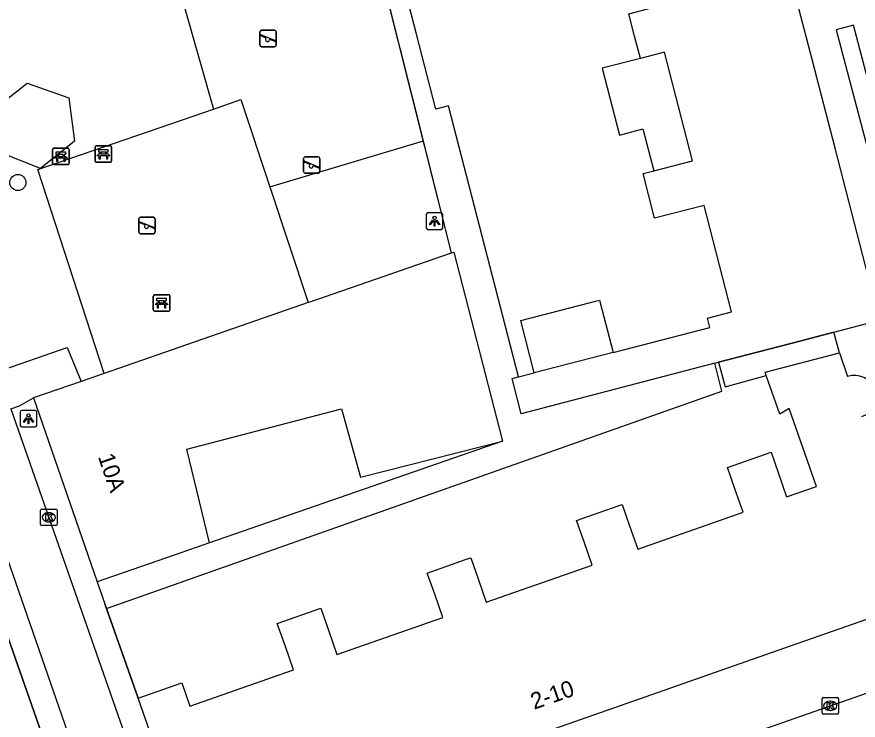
# Model space of a CAD drawing. Extents: x 159377 to 159983, y 382996 to 383595.
# Drawn here: x 159638.5 to 159689.6, y 383315.4 to 383358.1 of the extents above; entities that cross this region are included whole.
import ezdxf

# ---------------------------------------------------------------- set-up
doc = ezdxf.new("R2010")
doc.units = 0
for name, color, linetype in [('IMGEO_Bank', 7, 'Continuous'), ('IMGEO_Boom', 7, 'Continuous'), ('IMGEO_Groenvoorziening', 7, 'Continuous'), ('IMGEO_Hek', 7, 'Continuous'), ('IMGEO_Kolk', 7, 'Continuous'), ('IMGEO_Lichtpunt', 7, 'Continuous'), ('IMGEO_Muur', 7, 'Continuous'), ('IMGEO_Pand', 7, 'Continuous'), ('IMGEO_Pand_nummerreeks', 7, 'Continuous'), ('IMGEO_Pand_overbouw', 7, 'Continuous'), ('IMGEO_Rijbaan_lokaal_open', 7, 'Continuous'), ('IMGEO_Speelvoorziening', 7, 'Continuous'), ('IMGEO_Terreindeel_gesloten', 7, 'Continuous'), ('IMGEO_Voetpad_open', 7, 'Continuous')]:
    doc.layers.add(name, color=color, linetype=linetype)

msp = doc.modelspace()

# ---------------------------------------------------------------- linework, layer by layer
at = {"layer": 'IMGEO_Bank'}
for p, q in [((159643.349, 383350.24), (159644.19, 383350.24)), ((159644.19, 383350.24), (159643.349, 383350.24)), ((159640.697, 383349.171), (159640.697, 383350.012)), ((159640.697, 383350.012), (159640.697, 383349.171)), ((159640.772, 383350.096), (159641.613, 383350.096)), ((159641.613, 383350.096), (159640.772, 383350.096)), ((159641.338, 383349.714), (159641.056, 383349.714)), ((159641.697, 383350.021), (159641.697, 383349.18)), ((159641.697, 383349.18), (159641.697, 383350.021)), ((159643.274, 383349.315), (159643.274, 383350.156)), ((159643.274, 383350.156), (159643.274, 383349.315)), ((159643.583, 383349.746), (159643.583, 383349.852)), ((159643.627, 383349.852), (159643.627, 383349.746)), ((159643.915, 383349.858), (159643.633, 383349.858)), ((159643.633, 383349.74), (159643.915, 383349.74)), ((159643.921, 383349.746), (159643.921, 383349.852)), ((159643.965, 383349.852), (159643.965, 383349.746)), ((159644.274, 383350.165), (159644.274, 383349.324)), ((159644.274, 383349.324), (159644.274, 383350.165)), ((159641.394, 383349.494), (159641.001, 383349.494)), ((159641.006, 383349.602), (159641.006, 383349.708)), ((159641.05, 383349.708), (159641.05, 383349.602)), ((159641.056, 383349.596), (159641.338, 383349.596)), ((159641.344, 383349.602), (159641.344, 383349.708)), ((159641.388, 383349.708), (159641.388, 383349.602)), ((159644.199, 383349.24), (159643.358, 383349.24)), ((159643.358, 383349.24), (159644.199, 383349.24)), ((159643.971, 383349.638), (159643.578, 383349.638)), ((159641.622, 383349.096), (159640.781, 383349.096)), ((159640.781, 383349.096), (159641.622, 383349.096)), ((159646.805, 383340.282), (159646.805, 383341.123)), ((159646.805, 383341.123), (159646.805, 383340.282)), ((159646.88, 383341.207), (159647.721, 383341.207)), ((159647.721, 383341.207), (159646.88, 383341.207)), ((159647.805, 383341.132), (159647.805, 383340.291)), ((159647.805, 383340.291), (159647.805, 383341.132)), ((159647.502, 383340.605), (159647.109, 383340.605)), ((159647.114, 383340.713), (159647.114, 383340.819)), ((159647.158, 383340.819), (159647.158, 383340.713)), ((159647.446, 383340.825), (159647.164, 383340.825)), ((159647.164, 383340.707), (159647.446, 383340.707)), ((159647.452, 383340.713), (159647.452, 383340.819)), ((159647.496, 383340.819), (159647.496, 383340.713)), ((159647.73, 383340.207), (159646.889, 383340.207)), ((159646.889, 383340.207), (159647.73, 383340.207))]:
    msp.add_line(p, q, dxfattribs=at)
for points in [[(159641, 383349.714), (159640.914, 383349.714), (159640.914, 383349.875), (159641.477, 383349.875), (159641.477, 383349.714), (159641.394, 383349.714)], [(159643.521, 383349.638), (159643.379, 383349.638), (159643.491, 383349.74), (159643.577, 383349.74)], [(159643.577, 383349.858), (159643.491, 383349.858), (159643.491, 383350.019), (159644.054, 383350.019), (159644.054, 383349.858), (159643.971, 383349.858)], [(159643.971, 383349.74), (159644.054, 383349.74), (159644.166, 383349.638), (159644.027, 383349.638)], [(159640.944, 383349.494), (159640.802, 383349.494), (159640.914, 383349.596), (159641, 383349.596)], [(159640.994, 383349.487), (159640.994, 383349.28), (159640.951, 383349.28), (159640.951, 383349.487)], [(159641.394, 383349.596), (159641.477, 383349.596), (159641.589, 383349.494), (159641.45, 383349.494)], [(159641.444, 383349.487), (159641.444, 383349.28), (159641.4, 383349.28), (159641.4, 383349.487)], [(159643.571, 383349.631), (159643.571, 383349.424), (159643.528, 383349.424), (159643.528, 383349.631)], [(159644.021, 383349.631), (159644.021, 383349.424), (159643.977, 383349.424), (159643.977, 383349.631)], [(159647.052, 383340.605), (159646.91, 383340.605), (159647.022, 383340.707), (159647.108, 383340.707)], [(159647.108, 383340.825), (159647.022, 383340.825), (159647.022, 383340.986), (159647.585, 383340.986), (159647.585, 383340.825), (159647.502, 383340.825)], [(159647.102, 383340.598), (159647.102, 383340.391), (159647.059, 383340.391), (159647.059, 383340.598)], [(159647.502, 383340.707), (159647.585, 383340.707), (159647.697, 383340.605), (159647.558, 383340.605)], [(159647.552, 383340.598), (159647.552, 383340.391), (159647.508, 383340.391), (159647.508, 383340.598)]]:
    msp.add_lwpolyline(points, dxfattribs=at)
for centre, radius, start, end in [((159643.352, 383350.162), 0.0779, 92.4484, 184.2845), ((159643.352, 383350.162), 0.0779, 92.4484, 184.2845), ((159644.196, 383350.162), 0.0779, 2.4484, 94.2845), ((159644.196, 383350.162), 0.0779, 2.4484, 94.2845), ((159640.775, 383350.018), 0.0779, 92.4484, 184.2845), ((159640.775, 383350.018), 0.0779, 92.4484, 184.2845), ((159640.999, 383349.707), 0.00671, 2.8957, 87.1043), ((159641.056, 383349.707), 0.00671, 92.8957, 177.1043), ((159641.338, 383349.707), 0.00671, 2.8957, 87.1043), ((159641.395, 383349.707), 0.00671, 92.8957, 177.1043), ((159641.619, 383350.018), 0.0779, 2.4484, 94.2845), ((159641.619, 383350.018), 0.0779, 2.4484, 94.2845), ((159643.576, 383349.851), 0.00671, 2.8957, 87.1043), ((159643.576, 383349.747), 0.00671, 272.8957, 357.1043), ((159643.633, 383349.851), 0.00671, 92.8957, 177.1043), ((159643.633, 383349.747), 0.00671, 182.8957, 267.1043), ((159643.915, 383349.851), 0.00671, 2.8957, 87.1043), ((159643.915, 383349.747), 0.00671, 272.8957, 357.1043), ((159643.972, 383349.851), 0.00671, 92.8957, 177.1043), ((159643.972, 383349.747), 0.00671, 182.8957, 267.1043), ((159640.944, 383349.487), 0.00671, 2.8957, 87.1043), ((159641.001, 383349.487), 0.00671, 92.8957, 177.1043), ((159640.999, 383349.603), 0.00671, 272.8957, 357.1043), ((159641.056, 383349.603), 0.00671, 182.8957, 267.1043), ((159641.338, 383349.603), 0.00671, 272.8957, 357.1043), ((159641.395, 383349.603), 0.00671, 182.8957, 267.1043), ((159641.393, 383349.487), 0.00671, 2.8957, 87.1043), ((159641.45, 383349.487), 0.00671, 92.8957, 177.1043), ((159643.352, 383349.318), 0.0779, 182.4484, 274.2845), ((159643.352, 383349.318), 0.0779, 182.4484, 274.2845), ((159643.521, 383349.631), 0.00671, 2.8957, 87.1043), ((159643.578, 383349.631), 0.00671, 92.8957, 177.1043), ((159643.97, 383349.631), 0.00671, 2.8957, 87.1043), ((159644.027, 383349.631), 0.00671, 92.8957, 177.1043), ((159644.196, 383349.318), 0.0779, 272.4484, 4.2845), ((159644.196, 383349.318), 0.0779, 272.4484, 4.2845), ((159640.775, 383349.174), 0.0779, 182.4484, 274.2845), ((159640.775, 383349.174), 0.0779, 182.4484, 274.2845), ((159641.619, 383349.174), 0.0779, 272.4484, 4.2845), ((159641.619, 383349.174), 0.0779, 272.4484, 4.2845), ((159646.883, 383341.129), 0.0779, 92.4484, 184.2845), ((159646.883, 383341.129), 0.0779, 92.4484, 184.2845), ((159647.727, 383341.129), 0.0779, 2.4484, 94.2845), ((159647.727, 383341.129), 0.0779, 2.4484, 94.2845), ((159647.052, 383340.598), 0.00671, 2.8957, 87.1043), ((159647.109, 383340.598), 0.00671, 92.8957, 177.1043), ((159647.107, 383340.818), 0.00671, 2.8957, 87.1043), ((159647.107, 383340.714), 0.00671, 272.8957, 357.1043), ((159647.164, 383340.818), 0.00671, 92.8957, 177.1043), ((159647.164, 383340.714), 0.00671, 182.8957, 267.1043), ((159647.446, 383340.818), 0.00671, 2.8957, 87.1043), ((159647.446, 383340.714), 0.00671, 272.8957, 357.1043), ((159647.503, 383340.818), 0.00671, 92.8957, 177.1043), ((159647.503, 383340.714), 0.00671, 182.8957, 267.1043), ((159647.501, 383340.598), 0.00671, 2.8957, 87.1043), ((159647.558, 383340.598), 0.00671, 92.8957, 177.1043), ((159646.883, 383340.285), 0.0779, 182.4484, 274.2845), ((159646.883, 383340.285), 0.0779, 182.4484, 274.2845), ((159647.727, 383340.285), 0.0779, 272.4484, 4.2845), ((159647.727, 383340.285), 0.0779, 272.4484, 4.2845)]:
    msp.add_arc(centre, radius, start, end, dxfattribs=at)
at = {"layer": 'IMGEO_Boom'}
msp.add_circle((159638.589, 383348.008), 0.489, dxfattribs=at)
at = {"layer": 'IMGEO_Groenvoorziening'}
for points in [[(159660.333, 383361.889), (159648.673, 383358.7), (159650.451, 383352.464)], [(159643.825, 383336.433), (159639.809, 383348.793), (159650.451, 383352.464)], [(159653.87, 383347.749), (159663.189, 383350.536)], [(159653.87, 383347.749), (159656.195, 383340.726)]]:
    msp.add_lwpolyline(points, dxfattribs=at)
at = {"layer": 'IMGEO_Hek'}
msp.add_lwpolyline([(159664.897, 383343.747), (159659.23, 383366.272), (159657.585, 383372.81), (159655.247, 383382.105), (159644.328, 383379.336), (159643.576, 383379.146), (159638.181, 383377.778), (159637.69, 383377.722), (159635.326, 383377.454)], dxfattribs=at)
at = {"layer": 'IMGEO_Kolk'}
for p, q in [((159639.968, 383327.274), (159639.968, 383328.126)), ((159640.043, 383328.2), (159640.895, 383328.2)), ((159640.456, 383327.98), (159640.481, 383327.98)), ((159640.969, 383328.126), (159640.969, 383327.274)), ((159640.479, 383327.42), (159640.454, 383327.42)), ((159640.895, 383327.2), (159640.043, 383327.2)), ((159687.366, 383315.838), (159687.366, 383316.69)), ((159687.441, 383316.764), (159688.293, 383316.764)), ((159687.854, 383316.544), (159687.879, 383316.544)), ((159688.367, 383316.69), (159688.367, 383315.838)), ((159688.293, 383315.764), (159687.441, 383315.764)), ((159687.877, 383315.984), (159687.852, 383315.984))]:
    msp.add_line(p, q, dxfattribs=at)
for points in [[(159639.968, 383327.274), (159639.968, 383328.126)], [(159640.043, 383328.2), (159640.895, 383328.2)], [(159640.289, 383327.9), (159640.412, 383327.9), (159640.412, 383327.749), (159640.542, 383327.9), (159640.706, 383327.9), (159640.56, 383327.749), (159640.713, 383327.5), (159640.561, 383327.5), (159640.476, 383327.664), (159640.412, 383327.597), (159640.412, 383327.5), (159640.289, 383327.5), (159640.289, 383327.9)], [(159640.969, 383328.126), (159640.969, 383327.274)], [(159640.895, 383327.2), (159640.043, 383327.2)], [(159687.366, 383315.838), (159687.366, 383316.69)], [(159687.441, 383316.764), (159688.293, 383316.764)], [(159688.367, 383316.69), (159688.367, 383315.838)], [(159687.687, 383316.464), (159687.81, 383316.464), (159687.81, 383316.313), (159687.94, 383316.464), (159688.104, 383316.464), (159687.958, 383316.313), (159688.111, 383316.064), (159687.959, 383316.064), (159687.874, 383316.228), (159687.81, 383316.161), (159687.81, 383316.064), (159687.687, 383316.064), (159687.687, 383316.464)], [(159688.293, 383315.764), (159687.441, 383315.764)]]:
    msp.add_lwpolyline(points, dxfattribs=at)
for centre, start, end in [((159640.045, 383328.124), 91.552, 178.448), ((159640.045, 383328.124), 91.552, 178.448), ((159640.893, 383328.124), 1.552, 88.448), ((159640.893, 383328.124), 1.552, 88.448), ((159640.045, 383327.276), 181.552, 268.448), ((159640.045, 383327.276), 181.552, 268.448), ((159640.893, 383327.276), 271.552, 358.448), ((159640.893, 383327.276), 271.552, 358.448), ((159687.443, 383316.688), 91.552, 178.448), ((159687.443, 383316.688), 91.552, 178.448), ((159688.291, 383316.688), 1.552, 88.448), ((159688.291, 383316.688), 1.552, 88.448), ((159687.443, 383315.84), 181.552, 268.448), ((159687.443, 383315.84), 181.552, 268.448), ((159688.291, 383315.84), 271.552, 358.448), ((159688.291, 383315.84), 271.552, 358.448)]:
    msp.add_arc(centre, 0.0765, start, end, dxfattribs=at)
for centre, major_axis, ratio, start_param, end_param in [((159640.455, 383327.7), (-0.387, 0.002), 0.722429, 4.712389, 7.853982), ((159640.48, 383327.7), (-0.39, 0.002), 0.717154, 1.570796, 4.712389), ((159687.853, 383316.264), (-0.387, 0.002), 0.722429, 4.712389, 7.853982), ((159687.878, 383316.264), (-0.39, 0.002), 0.717154, 1.570796, 4.712389)]:
    msp.add_ellipse(centre, major_axis=major_axis, ratio=ratio, start_param=start_param, end_param=end_param, dxfattribs=at)
at = {"layer": 'IMGEO_Lichtpunt'}
for p, q in [((159664.265, 383346.164), (159663.457, 383346.164)), ((159664.265, 383346.164), (159663.457, 383346.164)), ((159663.363, 383346.069), (159663.363, 383345.262)), ((159663.363, 383346.069), (159663.363, 383345.262)), ((159664.359, 383345.262), (159664.359, 383346.069)), ((159664.359, 383345.262), (159664.359, 383346.069)), ((159663.457, 383345.168), (159664.265, 383345.168)), ((159663.457, 383345.168), (159664.265, 383345.168)), ((159638.734, 383334.085), (159638.734, 383333.278)), ((159638.734, 383334.085), (159638.734, 383333.278)), ((159639.636, 383334.18), (159638.828, 383334.18)), ((159639.636, 383334.18), (159638.828, 383334.18)), ((159639.73, 383333.278), (159639.73, 383334.085)), ((159639.73, 383333.278), (159639.73, 383334.085)), ((159638.828, 383333.184), (159639.636, 383333.184)), ((159638.828, 383333.184), (159639.636, 383333.184))]:
    msp.add_line(p, q, dxfattribs=at)
for points in [[(159663.737, 383345.733), (159663.776, 383345.705), (159663.588, 383345.443), (159663.55, 383345.47), (159663.737, 383345.733)], [(159663.839, 383345.685), (159663.886, 383345.685), (159663.886, 383345.363), (159663.839, 383345.363), (159663.839, 383345.685)], [(159663.949, 383345.705), (159663.987, 383345.732), (159664.174, 383345.47), (159664.135, 383345.442), (159663.949, 383345.705)], [(159639.108, 383333.749), (159639.147, 383333.721), (159638.959, 383333.459), (159638.921, 383333.486), (159639.108, 383333.749)], [(159639.21, 383333.701), (159639.257, 383333.701), (159639.257, 383333.379), (159639.21, 383333.379), (159639.21, 383333.701)], [(159639.32, 383333.721), (159639.358, 383333.748), (159639.545, 383333.486), (159639.506, 383333.458), (159639.32, 383333.721)]]:
    msp.add_lwpolyline(points, dxfattribs=at)
for centre in [(159663.862, 383345.867), (159639.233, 383333.883)]:
    msp.add_circle(centre, 0.0994, dxfattribs=at)
for centre, start, end in [((159663.457, 383346.069), 90, 180), ((159663.457, 383346.069), 90, 180), ((159664.265, 383346.069), 0, 90), ((159664.265, 383346.069), 0, 90), ((159663.457, 383345.262), 180, 270), ((159663.457, 383345.262), 180, 270), ((159664.265, 383345.262), 270, 0), ((159664.265, 383345.262), 270, 360), ((159638.828, 383334.085), 90, 180), ((159638.828, 383334.085), 90, 180), ((159639.636, 383334.085), 0, 90), ((159639.636, 383334.085), 0, 90), ((159638.828, 383333.278), 180, 270), ((159638.828, 383333.278), 180, 270), ((159639.636, 383333.278), 270, 0), ((159639.636, 383333.278), 270, 360)]:
    msp.add_arc(centre, 0.0946, start, end, dxfattribs=at)
at = {"layer": 'IMGEO_Muur'}
for points in [[(159645.886, 383316.734), (159643.889, 383322.392)], [(159638.001, 383320.394), (159639.998, 383314.666)]]:
    msp.add_lwpolyline(points, dxfattribs=at)
at = {"layer": 'IMGEO_Pand'}
for points in [[(159690.86, 383339.654), (159688.157, 383350.102), (159686.767, 383355.473), (159685.743, 383359.431), (159683.326, 383368.772), (159680.913, 383378.095), (159678.706, 383386.624)], [(159676.354, 383355.541), (159676.002, 383356.895), (159675.649, 383358.25), (159677.101, 383358.628), (159675.39, 383365.21), (159673.938, 383364.832), (159673.573, 383366.235), (159673.208, 383367.638), (159674.66, 383368.016), (159672.954, 383374.578), (159671.502, 383374.2), (159671.149, 383375.555), (159670.797, 383376.91), (159672.249, 383377.288), (159671.084, 383381.762), (159668.082, 383380.988), (159667.381, 383383.709)], [(159677.16, 383348.727), (159679.518, 383349.332), (159677.806, 383355.919), (159676.354, 383355.541)], [(159676.354, 383355.541), (159674.036, 383354.938), (159675.089, 383350.892), (159676.501, 383351.259), (159677.16, 383348.727)], [(159674.688, 383337.697), (159680.57, 383339.216), (159680.423, 383339.788), (159681.876, 383340.163), (159680.216, 383346.612), (159677.214, 383345.838), (159676.864, 383347.199), (159676.514, 383348.561), (159677.16, 383348.727)], [(159656.195, 383340.726), (159664.897, 383343.747)], [(159664.897, 383343.747), (159665.023, 383343.791), (159667.985, 383332.318)], [(159656.195, 383340.726), (159643.825, 383336.433)], [(159669.913, 383336.464), (159669.094, 383339.639), (159673.869, 383340.872), (159674.688, 383337.697)], [(159680.855, 383337.044), (159681.087, 383337.105), (159686.022, 383338.392), (159688.088, 383338.931), (159690.86, 383339.654)], [(159645.886, 383316.734), (159648.529, 383317.662), (159649.026, 383316.247), (159655.31, 383318.452), (159654.813, 383319.867), (159654.323, 383321.261), (159656.956, 383322.186), (159657.446, 383320.791), (159657.943, 383319.376), (159664.368, 383321.63), (159663.871, 383323.045), (159663.422, 383324.323), (159665.733, 383325.134), (159666.055, 383325.247), (159666.504, 383323.969), (159667.001, 383322.554), (159673.427, 383324.809), (159672.93, 383326.224), (159672.48, 383327.504), (159675.01, 383328.393), (159675.245, 383328.475), (159675.695, 383327.194), (159676.192, 383325.779), (159682.58, 383328.021), (159682.083, 383329.436), (159681.632, 383330.719), (159684.274, 383331.647), (159684.725, 383330.363), (159685.222, 383328.948), (159687.024, 383329.58), (159685.365, 383334.308), (159684.802, 383333.961), (159683.983, 383336.301), (159683.914, 383336.498), (159688.42, 383337.68), (159688.919, 383336.237)], [(159674.688, 383337.697), (159669.913, 383336.464)], [(159680.855, 383337.044), (159669.113, 383333.981), (159668.563, 383336.116), (159668.955, 383336.217)], [(159668.955, 383336.217), (159669.913, 383336.464)], [(159642.421, 383335.945), (159639.534, 383334.943)], [(159643.825, 383336.433), (159642.421, 383335.945)], [(159639.534, 383334.943), (159643.399, 383323.78)], [(159650.209, 383326.145), (159648.831, 383331.841), (159658.222, 383334.284), (159659.367, 383330.135), (159667.985, 383332.318)], [(159650.209, 383326.145), (159648.123, 383325.421), (159643.399, 383323.78)], [(159695.046, 383323.244), (159685.437, 383319.879), (159676.282, 383316.672), (159667.221, 383313.499), (159658.161, 383310.326), (159649.218, 383307.194)], [(159649.218, 383307.194), (159645.886, 383316.734)]]:
    msp.add_lwpolyline(points, dxfattribs=at)
msp.add_arc((159689.335, 383335.018), 1.288, 290.5674, 108.836, dxfattribs=at)
at = {"layer": 'IMGEO_Pand_overbouw'}
msp.add_lwpolyline([(159688.42, 383337.68), (159688.088, 383338.931), (159686.022, 383338.392), (159681.087, 383337.105), (159681.487, 383335.612), (159683.983, 383336.301), (159683.914, 383336.498)], close=True, dxfattribs=at)
at = {"layer": 'IMGEO_Rijbaan_lokaal_open'}
for points in [[(159638.165, 383334.29), (159647.812, 383306.694)], [(159644.757, 383305.615), (159635.142, 383333.243)]]:
    msp.add_lwpolyline(points, dxfattribs=at)
at = {"layer": 'IMGEO_Speelvoorziening'}
for p, q in [((159653.274, 383356.343), (159653.274, 383357.143)), ((159653.274, 383357.143), (159653.274, 383356.343)), ((159653.657, 383356.771), (159653.318, 383356.908)), ((159653.343, 383356.968), (159654.219, 383356.615)), ((159653.374, 383357.243), (159654.164, 383357.243)), ((159654.164, 383357.243), (159653.374, 383357.243)), ((159654.264, 383357.143), (159654.264, 383356.343)), ((159654.264, 383356.343), (159654.264, 383357.143)), ((159654.195, 383356.555), (159653.855, 383356.692)), ((159654.164, 383356.243), (159653.374, 383356.243)), ((159653.374, 383356.243), (159654.164, 383356.243)), ((159655.916, 383348.671), (159655.916, 383349.471)), ((159655.916, 383349.471), (159655.916, 383348.671)), ((159656.299, 383349.099), (159655.96, 383349.236)), ((159655.985, 383349.296), (159656.861, 383348.943)), ((159656.016, 383349.571), (159656.806, 383349.571)), ((159656.806, 383349.571), (159656.016, 383349.571)), ((159656.906, 383349.471), (159656.906, 383348.671)), ((159656.906, 383348.671), (159656.906, 383349.471)), ((159656.837, 383348.883), (159656.497, 383349.02)), ((159656.806, 383348.571), (159656.016, 383348.571)), ((159656.016, 383348.571), (159656.806, 383348.571)), ((159645.925, 383345.007), (159645.925, 383345.807)), ((159645.925, 383345.807), (159645.925, 383345.007)), ((159645.994, 383345.632), (159646.87, 383345.279)), ((159646.025, 383345.907), (159646.815, 383345.907)), ((159646.815, 383345.907), (159646.025, 383345.907)), ((159646.915, 383345.807), (159646.915, 383345.007)), ((159646.915, 383345.007), (159646.915, 383345.807)), ((159646.308, 383345.435), (159645.969, 383345.572)), ((159646.846, 383345.219), (159646.506, 383345.356)), ((159646.815, 383344.907), (159646.025, 383344.907)), ((159646.025, 383344.907), (159646.815, 383344.907))]:
    msp.add_line(p, q, dxfattribs=at)
for centre, radius, start, end in [((159653.374, 383357.143), 0.1, 90, 180), ((159653.374, 383357.143), 0.1, 90, 180), ((159653.331, 383356.938), 0.0327, 68.078, 248.078), ((159654.164, 383357.143), 0.1, 0, 90), ((159654.164, 383357.143), 0.1, 360, 90), ((159653.736, 383356.681), 0.12, 130.9928, 5.1632), ((159654.207, 383356.585), 0.0327, 248.078, 68.078), ((159653.374, 383356.343), 0.1, 180, 270), ((159653.374, 383356.343), 0.1, 180, 270), ((159654.164, 383356.343), 0.1, 270, 0), ((159654.164, 383356.343), 0.1, 270, 0), ((159656.016, 383349.471), 0.1, 90, 180), ((159656.016, 383349.471), 0.1, 90, 180), ((159655.973, 383349.266), 0.0327, 68.078, 248.078), ((159656.806, 383349.471), 0.1, 0, 90), ((159656.806, 383349.471), 0.1, 360, 90), ((159656.378, 383349.009), 0.12, 130.9928, 5.1632), ((159656.849, 383348.913), 0.0327, 248.078, 68.078), ((159656.016, 383348.671), 0.1, 180, 270), ((159656.016, 383348.671), 0.1, 180, 270), ((159656.806, 383348.671), 0.1, 270, 0), ((159656.806, 383348.671), 0.1, 270, 0), ((159646.025, 383345.807), 0.1, 90, 180), ((159646.025, 383345.807), 0.1, 90, 180), ((159645.982, 383345.602), 0.0327, 68.078, 248.078), ((159646.815, 383345.807), 0.1, 0, 90), ((159646.815, 383345.807), 0.1, 360, 90), ((159646.387, 383345.345), 0.12, 130.9928, 5.1632), ((159646.858, 383345.249), 0.0327, 248.078, 68.078), ((159646.025, 383345.007), 0.1, 180, 270), ((159646.025, 383345.007), 0.1, 180, 270), ((159646.815, 383345.007), 0.1, 270, 0), ((159646.815, 383345.007), 0.1, 270, 0)]:
    msp.add_arc(centre, radius, start, end, dxfattribs=at)
at = {"layer": 'IMGEO_Terreindeel_gesloten'}
msp.add_lwpolyline([(159650.451, 383352.464), (159652.119, 383353.038), (159653.87, 383347.749)], dxfattribs=at)
at = {"layer": 'IMGEO_Voetpad_open'}
for points in [[(159668.955, 383336.217), (159664.71, 383352.656), (159663.933, 383352.456), (159662.762, 383357.003), (159661.386, 383362.347), (159662.051, 383362.518), (159657.266, 383381.105), (159667.381, 383383.709)], [(159663.189, 383350.536), (159660.333, 383361.889)], [(159688.224, 383357.272), (159690.694, 383347.929), (159691.743, 383348.213), (159689.269, 383357.553), (159688.224, 383357.272)], [(159637.104, 383352.444), (159639.161, 383354.045), (159641.673, 383353.15), (159642.022, 383350.52), (159639.958, 383348.855), (159637.503, 383349.835), (159637.104, 383352.444)], [(159664.897, 383343.747), (159663.189, 383350.536)], [(159626.42, 383347.465), (159628.027, 383343.101), (159634.849, 383345.441), (159636.979, 383339.231), (159636.397, 383338.982), (159637.249, 383336.509), (159641.583, 383337.997), (159642.421, 383335.945)], [(159643.966, 383322.174), (159681.296, 383335.353), (159680.855, 383337.044)], [(159638.165, 383334.29), (159638.685, 383334.47), (159639.534, 383334.943)], [(159667.985, 383332.318), (159650.209, 383326.145)], [(159643.399, 383323.78), (159643.889, 383322.392), (159643.966, 383322.174)], [(159643.966, 383322.174), (159645.886, 383316.734)], [(159639.998, 383314.666), (159638.001, 383320.394), (159611.994, 383311.273), (159611.905, 383311.499)], [(159665.099, 383305.268), (159664.149, 383307.952), (159691.347, 383317.482), (159692.313, 383314.752)]]:
    msp.add_lwpolyline(points, dxfattribs=at)

# ---------------------------------------------------------------- texts
at = {"layer": 'IMGEO_Pand_nummerreeks'}
for s, rotation, p in [('10A', 289.0965, (159643.434, 383331.381)), ('2-10', 19.2972, (159669.901, 383316.027))]:
    msp.add_text(s, height=1, rotation=rotation, dxfattribs=at).set_placement(p)

doc.saveas('drawing.dxf')
